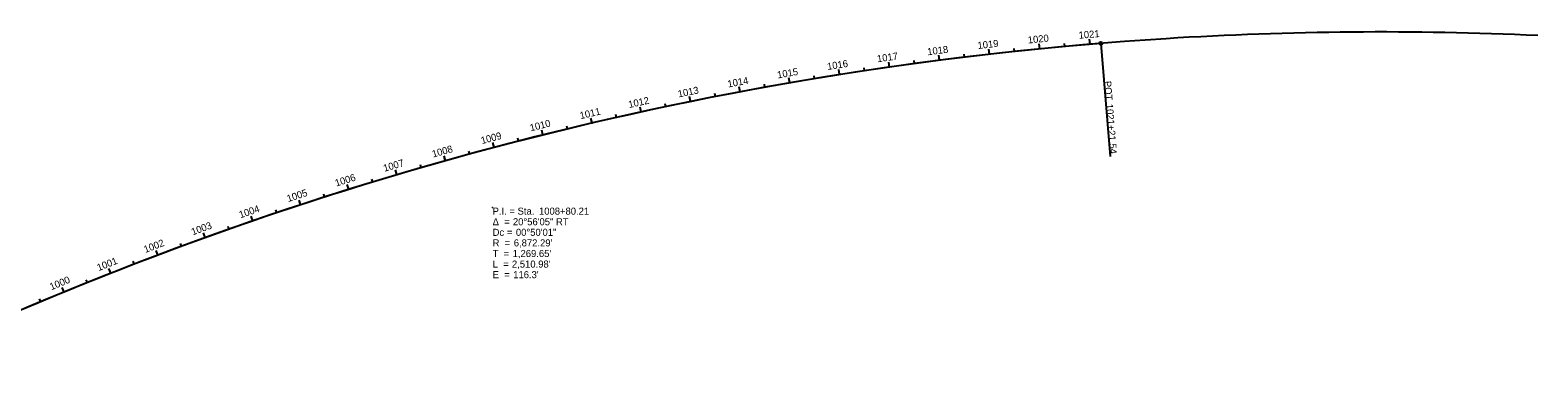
# Model space of a CAD drawing. Extents: x 2192013 to 2197996, y 660216 to 661764.
# Drawn here: x 2195008 to 2197996, y 661086 to 661764 of the extents above; entities that cross this region are included whole.
import ezdxf

# ---------------------------------------------------------------- set-up
doc = ezdxf.new("R2010")
doc.units = 0
for name, color, linetype in [('Default', 7, 'Continuous'), ('GE_X_Alignment', 7, 'Continuous'), ('GE_X_Alignment_1000_Curve_Data', 7, 'Continuous'), ('GE_X_Alignment_1000_Stations', 7, 'Continuous'), ('GE_X_Alignment_100_Curve_Data', 7, 'Continuous'), ('GE_X_Alignment_100_Stations', 7, 'Continuous'), ('GE_X_Alignment_500_Curve_Data', 7, 'Continuous'), ('GE_X_Alignment_500_Stations', 7, 'Continuous')]:
    doc.layers.add(name, color=color, linetype=linetype)

msp = doc.modelspace()

# ---------------------------------------------------------------- linework, layer by layer
at = {"layer": 'Default'}
for centre in [(2197009, 661726.4), (2197009, 661726.4), (2197009, 661726.4), (2197108.6, 661735.5), (2197130, 661737.3), (2197130, 661737.3), (2197130, 661737.3), (2196711.2, 661690.2), (2196810.3, 661703.7), (2196909.5, 661715.8), (2196513.7, 661658.9), (2196513.7, 661658.9), (2196612.3, 661675.3), (2196415.3, 661641.1), (2196219.3, 661601.2), (2196317.1, 661621.9), (2196121.7, 661579.1), (2196024.5, 661555.6), (2196024.5, 661555.6), (2196024.5, 661555.6), (2195927.7, 661530.7), (2195831.2, 661504.4), (2195735.1, 661476.7), (2195639.5, 661447.6), (2195544.2, 661417.1), (2195544.2, 661417.1), (2195924.7, 661411.6), (2195924.7, 661411.6), (2195924.7, 661411.6), (2195449.5, 661385.2), (2195355.2, 661352), (2195261.3, 661317.3), (2195168, 661281.3), (2195075.3, 661244), (2195075.3, 661244), (2195075.3, 661244)]:
    msp.add_circle(centre, 0.0000833, dxfattribs=at)
at = {"layer": 'GE_X_Alignment'}
for centre, radius, start, end in [((2197685.6, 654925), 6834.9, 87.39548, 93.57492), ((2197687.9, 654887.7), 6872.3, 93.57492, 115.59075), ((2197687.9, 654887.7), 6872.3, 94.65616, 115.59075)]:
    msp.add_arc(centre, radius, start, end, dxfattribs=at)
at = {"layer": 'GE_X_Alignment_1000_Stations'}
for p, q in [((2197009, 661726.4), (2197008, 661736.3)), ((2197130, 661737.3), (2197148.3, 661513)), ((2196513.7, 661658.9), (2196512.6, 661664.8)), ((2196024.5, 661555.6), (2196022.1, 661565.4)), ((2195544.2, 661417.1), (2195542.4, 661422.8)), ((2195075.3, 661244), (2195071.5, 661253.2))]:
    msp.add_line(p, q, dxfattribs=at)
msp.add_circle((2197130, 661737.3), 3, dxfattribs=at)
at = {"layer": 'GE_X_Alignment_100_Stations'}
for p, q in [((2196909.5, 661715.8), (2196908.4, 661725.7)), ((2196959.2, 661721.2), (2196958.6, 661727.2)), ((2197009, 661726.4), (2197008, 661736.3)), ((2197058.7, 661731.1), (2197058.2, 661737.1)), ((2197108.6, 661735.5), (2197107.7, 661745.5)), ((2197130, 661737.3), (2197148.3, 661513)), ((2196661.7, 661682.9), (2196660.8, 661688.9)), ((2196711.2, 661690.2), (2196709.8, 661700.1)), ((2196760.7, 661697.1), (2196759.9, 661703.1)), ((2196810.3, 661703.7), (2196809, 661713.6)), ((2196859.9, 661709.9), (2196859.2, 661715.9)), ((2196513.7, 661658.9), (2196511.9, 661668.8)), ((2196562.9, 661667.3), (2196562, 661673.2)), ((2196612.3, 661675.3), (2196610.7, 661685.2)), ((2196317.1, 661621.9), (2196315.1, 661631.7)), ((2196366.2, 661631.7), (2196365, 661637.6)), ((2196415.3, 661641.1), (2196413.4, 661650.9)), ((2196464.4, 661650.2), (2196463.4, 661656.1)), ((2196219.3, 661601.2), (2196217.1, 661611)), ((2196268.2, 661611.7), (2196266.9, 661617.6)), ((2196073.1, 661567.6), (2196071.7, 661573.4)), ((2196121.7, 661579.1), (2196119.5, 661588.9)), ((2196170.5, 661590.4), (2196169.1, 661596.2)), ((2195927.7, 661530.7), (2195925.1, 661540.4)), ((2195976.1, 661543.4), (2195974.6, 661549.2)), ((2196024.5, 661555.6), (2196022.1, 661565.4)), ((2195831.2, 661504.4), (2195828.5, 661514.1)), ((2195879.4, 661517.8), (2195877.8, 661523.5)), ((2195735.1, 661476.7), (2195732.3, 661486.3)), ((2195783.1, 661490.7), (2195781.5, 661496.5)), ((2195639.5, 661447.6), (2195636.5, 661457.1)), ((2195687.3, 661462.3), (2195685.5, 661468.1)), ((2195544.2, 661417.1), (2195541.1, 661426.6)), ((2195591.8, 661432.5), (2195590, 661438.2)), ((2195449.5, 661385.2), (2195446.2, 661394.7)), ((2195496.8, 661401.3), (2195494.9, 661407)), ((2195355.2, 661352), (2195351.8, 661361.4)), ((2195402.2, 661368.8), (2195400.3, 661374.4)), ((2195308.2, 661334.8), (2195306.1, 661340.4)), ((2195214.6, 661299.5), (2195212.5, 661305.1)), ((2195261.3, 661317.3), (2195257.8, 661326.7)), ((2195168, 661281.3), (2195164.4, 661290.6)), ((2195075.3, 661244), (2195071.5, 661253.2)), ((2195121.6, 661262.8), (2195119.4, 661268.4)), ((2195029.1, 661224.8), (2195026.8, 661230.4))]:
    msp.add_line(p, q, dxfattribs=at)
msp.add_circle((2197130, 661737.3), 3, dxfattribs=at)
at = {"layer": 'GE_X_Alignment_500_Stations'}
for p, q in [((2196909.5, 661715.8), (2196908.9, 661721.7)), ((2197009, 661726.4), (2197008, 661736.3)), ((2197108.6, 661735.5), (2197108, 661741.5)), ((2197130, 661737.3), (2197148.3, 661513)), ((2196711.2, 661690.2), (2196710.3, 661696.2)), ((2196810.3, 661703.7), (2196809.5, 661709.7)), ((2196513.7, 661658.9), (2196511.9, 661668.8)), ((2196612.3, 661675.3), (2196611.4, 661681.2)), ((2196415.3, 661641.1), (2196414.1, 661647)), ((2196219.3, 661601.2), (2196218, 661607.1)), ((2196317.1, 661621.9), (2196315.9, 661627.8)), ((2196121.7, 661579.1), (2196120.4, 661585)), ((2196024.5, 661555.6), (2196022.1, 661565.4)), ((2195831.2, 661504.4), (2195829.6, 661510.2)), ((2195927.7, 661530.7), (2195926.2, 661536.5)), ((2195735.1, 661476.7), (2195733.4, 661482.5)), ((2195639.5, 661447.6), (2195637.7, 661453.3)), ((2195544.2, 661417.1), (2195541.1, 661426.6)), ((2195449.5, 661385.2), (2195447.5, 661390.9)), ((2195355.2, 661352), (2195353.1, 661357.6)), ((2195261.3, 661317.3), (2195259.2, 661322.9)), ((2195168, 661281.3), (2195165.8, 661286.9)), ((2195075.3, 661244), (2195071.5, 661253.2))]:
    msp.add_line(p, q, dxfattribs=at)
msp.add_circle((2197130, 661737.3), 3, dxfattribs=at)

# ---------------------------------------------------------------- texts
at = {"layer": 'GE_X_Alignment_1000_Curve_Data'}
for s, p in [('Δ  = ', (2195924.7, 661376.6)), ('P.I. = Sta. ', (2195924.7, 661397.6)), ('20°56\'05" RT', (2195964.9, 661376.6)), ('1008+80.21', (2196016.6, 661397.6)), ('Dc = ', (2195924.7, 661355.6)), ('00°50\'01"', (2195970.9, 661355.6)), ('R  = ', (2195924.7, 661334.6)), ("6,872.29'", (2195966.6, 661334.6)), ('T  = ', (2195924.7, 661313.6)), ('L  = ', (2195924.7, 661292.6)), ("2,510.98'", (2195963, 661292.6)), ("1,269.65'", (2195964.4, 661313.6)), ('E  = ', (2195924.7, 661271.6)), ("116.3'", (2195965.5, 661271.6))]:
    msp.add_text(s, height=14, dxfattribs=at).set_placement(p)
at = {"layer": 'GE_X_Alignment_1000_Stations'}
for s, rotation, p in [('1020', 5.6695, (2196986, 661736.9)), ('POT', 274.6562, (2197136.4, 661662.2)), ('1021+21.54', 274.6562, (2197140.1, 661616.7)), ('1010', 14.0067, (2196000.3, 661562.7)), ('1000', 22.3439, (2195050.2, 661247.5))]:
    msp.add_text(s, height=14, rotation=rotation, dxfattribs=at).set_placement(p)
at = {"layer": 'GE_X_Alignment_100_Curve_Data'}
for s, p in [('Δ  = ', (2195924.7, 661376.6)), ('P.I. = Sta. ', (2195924.7, 661397.6)), ('20°56\'05" RT', (2195964.9, 661376.6)), ('1008+80.21', (2196016.6, 661397.6)), ('Dc = ', (2195924.7, 661355.6)), ('00°50\'01"', (2195970.9, 661355.6)), ('R  = ', (2195924.7, 661334.6)), ("6,872.29'", (2195966.6, 661334.6)), ('T  = ', (2195924.7, 661313.6)), ('L  = ', (2195924.7, 661292.6)), ("2,510.98'", (2195963, 661292.6)), ("1,269.65'", (2195964.4, 661313.6)), ('E  = ', (2195924.7, 661271.6)), ("116.3'", (2195965.5, 661271.6))]:
    msp.add_text(s, height=14, dxfattribs=at).set_placement(p)
at = {"layer": 'GE_X_Alignment_100_Stations'}
for s, rotation, p in [('1020', 5.6695, (2196986, 661736.9)), ('1021', 4.8358, (2197086.6, 661746.4)), ('1017', 8.1707, (2196687.5, 661699.7)), ('1018', 7.3369, (2196787, 661713.6)), ('1019', 6.5032, (2196886.5, 661726)), ('1015', 9.8381, (2196489.9, 661667.7)), ('1016', 9.0044, (2196588.7, 661684.4)), ('1014', 10.6718, (2196391.6, 661649.6)), ('POT', 274.6562, (2197136.4, 661662.2)), ('1012', 12.3393, (2196195.3, 661609)), ('1013', 11.5056, (2196293.3, 661630)), ('1011', 13.173, (2196099.1, 661586.9)), ('1021+21.54', 274.6562, (2197140.1, 661616.7)), ('1010', 14.0067, (2196000.3, 661562.7)), ('1009', 14.8404, (2195903.5, 661537.5)), ('1008', 15.6742, (2195806.8, 661510.8)), ('1007', 16.5079, (2195710.3, 661482.6)), ('1006', 17.3416, (2195614.8, 661453.2)), ('1005', 18.1753, (2195519.5, 661422.4)), ('1004', 19.0091, (2195424.9, 661390.2)), ('1003', 19.8428, (2195330.4, 661356.5)), ('1002', 20.6765, (2195236.4, 661321.5)), ('1001', 21.5102, (2195143.8, 661285.5)), ('1000', 22.3439, (2195050.2, 661247.5))]:
    msp.add_text(s, height=14, rotation=rotation, dxfattribs=at).set_placement(p)
at = {"layer": 'GE_X_Alignment_500_Curve_Data'}
for s, p in [('Δ  = ', (2195924.7, 661376.6)), ('P.I. = Sta. ', (2195924.7, 661397.6)), ('20°56\'05" RT', (2195964.9, 661376.6)), ('1008+80.21', (2196016.6, 661397.6)), ('Dc = ', (2195924.7, 661355.6)), ('00°50\'01"', (2195970.9, 661355.6)), ('R  = ', (2195924.7, 661334.6)), ("6,872.29'", (2195966.6, 661334.6)), ('T  = ', (2195924.7, 661313.6)), ('L  = ', (2195924.7, 661292.6)), ("2,510.98'", (2195963, 661292.6)), ("1,269.65'", (2195964.4, 661313.6)), ('E  = ', (2195924.7, 661271.6)), ("116.3'", (2195965.5, 661271.6))]:
    msp.add_text(s, height=14, dxfattribs=at).set_placement(p)
at = {"layer": 'GE_X_Alignment_500_Stations'}
for s, rotation, p in [('1020', 5.6695, (2196986, 661736.9)), ('1015', 9.8381, (2196489.9, 661667.7)), ('POT', 274.6562, (2197136.4, 661662.2)), ('1021+21.54', 274.6562, (2197140.1, 661616.7)), ('1010', 14.0067, (2196000.3, 661562.7)), ('1005', 18.1753, (2195519.5, 661422.4)), ('1000', 22.3439, (2195050.2, 661247.5))]:
    msp.add_text(s, height=14, rotation=rotation, dxfattribs=at).set_placement(p)

doc.saveas('drawing.dxf')
